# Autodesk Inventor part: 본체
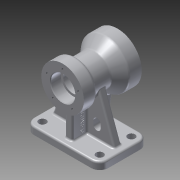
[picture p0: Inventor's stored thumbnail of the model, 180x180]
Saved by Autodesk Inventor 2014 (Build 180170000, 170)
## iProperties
Created: 2015-08
Part Number: 본체
Material: 알루미늄 6061
Document SubType Name: Modeling
Designer: SCD-A09
Density: 2.71 g/cm^3
Appearance: 알루미늄 - 평지
Mass: 1062.37 g
Surface Area: 750.557 cm^2
Volume: 392.018 cm^3
Author: SCD-A09
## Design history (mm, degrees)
sketch "스케치1"
  geometry: L1 (-61, 40)-(61, 40); L2 (61, 40)-(61, -40); L3 (61, -40)-(-61, -40); L4 (-61, -40)-(-61, 40); L5 (-61, 40)-(61, -40); L6 (61, 40)-(-61, -40); 1 further point
  constraints: 12 end point, 2 midpoint, 2 parallel, 1 horizontal, 1 perpendicular
  dimensions: "d0" = 122 distance of L2.end L3.end; "d1" = 80 distance of L1.end L2.end
extrude "돌출1" new body sketch "스케치1" distance "d2" = 12; taper "d3" = 0 deg
fillet "모깎기1" dims "d4" = 14
fillet "모깎기2" dims "d5" = 3
sketch "스케치3"
  geometry: L1 (0, 40)-(9, 40) reference; L2 (90, 63.67)-(90, -74.186); L3 (0, 26)-(0, -26) reference; L4 (90, 40)-(125, 40); L5 (125, 40)-(125, 20); L6 (125, 20)-(116, 14.804); L7 (116, 14.804)-(116, -13.315); L8 (116, -13.315)-(130, -30); L9 (130, -30)-(130, -50); L10 (130, -50)-(90, -50); 1 further point
  constraints: 16 end point, 4 perpendicular, 3 point on line, 2 parallel
  dimensions: "d7" = 90 distance between parallel lines of L3 L2; "d8" = 70 diameter of L5 L2; "d9" = 52 diameter of L7 L2; "d10" = 80 diameter of L9 L2; "d11" = 20 distance of L4.end L5.end; "d12" = 20 distance of L8.end L9.end; "d13" = 60 deg angle of L7 L6; "d14" = 40 deg angle of L7 L8; "d15" = 90 distance between parallel lines of L10 L4
revolve "회전1" sketch "스케치3" stored, may be unused: angle "d16" = 90 deg
sketch "스케치4"
  geometry: L1 (61, 9)-(61, 0) reference; L2 (61, 0)-(-61, 0) reference; L3 (-61, 0)-(-61, 9) reference; L4 (-58, 12)-(58, 12) reference; L5 (51, 12)-(20.667, 95.339); L6 (-51, 12)-(-20.234, 96.53); L7 (20.667, 95.339)-(-20.234, 96.53); L8 (51, 12)-(-51, 12); C1 r 26 at (0, 90) reference; A1 r 3 centre (58, 9) between (61, 9) and (58, 12) reference; A2 r 3 centre (-58, 9) between (-58, 12) and (-61, 9) reference; 1 further point
  constraints: 8 end point, 2 point on line, 1 collinear
  dimensions: "d22" = 70 deg angle of L4 L5; "d23" = 70 deg angle of L4 L6; "d24" = 10 horizontal distance of L5.start L1.start; "d25" = 10 horizontal distance of L3.end L6.start
extrude "돌출2" join sketch "스케치4" stored distance "d26" = 12; taper "d27" = 0 deg
sketch "스케치5"
  geometry: L1 (12, 37)-(12, 6) reference; L2 (12, 6)-(64, 6) reference; L3 (64, 6)-(64, 14.804) reference; L4 (64, 14.804)-(55, 20) reference; L5 (55, 20)-(55, 40) reference; L6 (55, 40)-(125, 40) reference; L7 (125, 40)-(125, 20) reference; L8 (125, 20)-(116, 14.804) reference; L9 (116, 14.804)-(116, -13.315) reference; L10 (116, -13.315)-(130, -30) reference; L11 (130, -30)-(130, -50) reference; L12 (130, -50)-(50, -50) reference; L13 (50, -50)-(50, -30) reference; L14 (50, -30)-(64, -13.315) reference; L15 (64, -13.315)-(64, -6) reference; L16 (64, -6)-(12, -6) reference; L17 (12, -6)-(12, -37) reference; L18 (9, -40)-(0, -40) reference; L19 (0, -40)-(0, 40) reference; L20 (0, 40)-(9, 40) reference; L21 (12, 30)-(82.096, 30); L22 (82.096, 30)-(82.096, -42.36); L23 (82.096, -42.36)-(12, -30); L24 (12, 30)-(12, -30); A1 r 3 centre (9, 37) between (12, 37) and (9, 40) reference; A2 r 3 centre (9, -37) between (9, -40) and (12, -37) reference; 3 further points
  constraints: 8 end point, 5 point on line, 1 collinear, 1 parallel, 1 perpendicular
  dimensions: "d28" = 10 distance from line of L19.end L21; "d29" = 10 vertical distance of L18.start L23.end; "d30" = 80 deg angle of L17 L23
extrude "돌출3" join sketch "스케치5" stored distance "d31" = 12; taper "d32" = 0 deg
sketch "스케치6"
  geometry: C1 r 6 at (-47, -26); C2 r 6 at (-47, 26); C3 r 6 at (47, 26); C4 r 6 at (47, -26); A1 r 11 centre (-47, -26) between (-58, -26) and (-47, -37) reference; A2 r 11 centre (47, -26) between (47, -37) and (58, -26) reference; A3 r 11 centre (47, 26) between (58, 26) and (47, 37) reference; A4 r 11 centre (-47, 26) between (-47, 37) and (-58, 26) reference; 1 further point
  constraints: 4 centre point, 4 coincident
  dimensions: "d34" = 12 diameter of C1; "d35" = 12 diameter of C2; "d36" = 12 diameter of C3; "d37" = 12 diameter of C4
extrude "돌출4" cut sketch "스케치6" stored distance "d38" = 12; taper "d39" = 0 deg
sketch "스케치7"
  geometry: L1 (-6, 12)-(-6, 64.702) reference; L2 (-6, 12)-(-51, 12) reference; L3 (-58, 12)-(-51, 12) reference; L4 (-51, 12)-(-6, 12) reference; L5 (-6, 12)-(-6, 64.702) reference; L6 (-51, 12)-(-25.091, 83.185) reference; L7 (-61, 0)-(-61, 9) reference; L8 (61, 0)-(-61, 0) reference; L9 (61, 9)-(61, 0) reference; L10 (51, 12)-(58, 12) reference; L11 (6, 12)-(51, 12) reference; L12 (6, 64.702)-(6, 12) reference; L13 (25.091, 83.185)-(51, 12) reference; L14 (-22.5, 30)-(-22.5, 36); L15 (-28.5, 30)-(-28.5, 36); L16 (-16.5, 36)-(-16.5, 30); L17 (25.5, 30)-(25.5, 36); L18 (19.5, 30)-(19.5, 36); L19 (31.5, 36)-(31.5, 30); A1 r 26 centre (0, 90) between (-25.091, 83.185) and (-6, 64.702) reference; A2 r 26 centre (0, 90) between (-25.091, 83.185) and (-6, 64.702) reference; A3 r 3 centre (-58, 9) between (-58, 12) and (-61, 9) reference; A4 r 3 centre (58, 9) between (61, 9) and (58, 12) reference; A5 r 26 centre (0, 90) between (6, 64.702) and (25.091, 83.185) reference; A6 r 26 centre (0, 90) between (25.091, 83.185) and (-25.091, 83.185) reference; A7 r 6 centre (-22.5, 30) between (-28.5, 30) and (-16.5, 30); A8 r 6 centre (-22.5, 36) between (-16.5, 36) and (-28.5, 36); A9 r 6 centre (25.5, 30) between (19.5, 30) and (31.5, 30); A10 r 6 centre (25.5, 36) between (31.5, 36) and (19.5, 36); 3 further points
  constraints: 16 end point, 8 point on circle, 8 tangent, 5 parallel, 4 centre point, 2 midpoint, 1 equal radius, 1 horizontal alignment
  dimensions: "d41" = 12 distance between parallel lines of L16 L15; "d42" = 18 dimension on A7 A8; "d43" = 18 distance from line of L2 L14.start; "d44" = 48 distance of point (25.5, 33) point (-22.5, 33); "d45" = 22.5 horizontal distance of A1.centre point (-22.5, 33)
extrude "돌출5" cut sketch "스케치7" stored distance "d46" = 12; taper "d47" = 0 deg
fillet "모깎기3" dims "d48" = 5
fillet "모깎기4" dims "d49" = 3
fillet "모깎기5" dims "d50" = 3
sketch "스케치8"
  geometry: C1 r 40 at (0, 0) reference; C2 r 26 at (0, 0); 1 further point
  constraints: 1 centre point, 1 coincident
  dimensions: "d51" = 52 diameter of C2
extrude "돌출6" cut sketch "스케치8" distance "d52" = 20; taper "d53" = 0 deg
sketch "스케치9"
  geometry: C1 r 26 at (0, 0) reference; C2 r 19 at (0, 0); 1 further point
  constraints: 1 centre point, 1 coincident
  dimensions: "d54" = 38 diameter of C2
extrude "돌출7" cut sketch "스케치9" distance "d55" = 3; taper "d56" = 0 deg
sketch "스케치10"
  geometry: C1 r 35 at (0, 0) reference; C2 r 20 at (0, 0); 1 further point
  constraints: 1 centre point, 1 coincident
  dimensions: "d57" = 40 diameter of C2
extrude "돌출8" cut sketch "스케치10" distance "d58" = 17; taper "d59" = 0 deg
sketch "스케치11"
  geometry: C1 r 20 at (0, 0) reference; C2 r 16 at (0, 0); 1 further point
  constraints: 1 centre point, 1 coincident
  dimensions: "d60" = 32 diameter of C2
extrude "돌출9" cut sketch "스케치11" stored distance "d61" = 40; taper "d62" = 0 deg
sketch "스케치12" dims "d63" = 66
  geometry: C1 r 40 at (0, 0) reference; 7 further points
  constraints: 1 coincident, 1 vertical alignment, 8 other
  dimensions: "d66" = 360 deg dimension on point (0, 0) point (0, 33) (derived)
hole "구멍1" sketch "스케치12" at (0, 33), (-31.385, 10.198), (-19.397, -26.698), (19.397, -26.698), (31.385, 10.198) diameter "d68" = 3.459; stored, may be unused: countersink angle "d72" = 90 deg, drill point angle "d74" = 118 deg; dims "d69" = 10, "d70" = 4, "d71" = 2, "d73" = 13
sketch "스케치13" dims "d75" = 54
  geometry: C1 r 35 at (0, 0) reference; 7 further points
  constraints: 1 coincident, 1 vertical alignment, 8 other
  dimensions: "d78" = 360 deg dimension on point (0, 0) point (0, 27) (derived)
hole "구멍2" sketch "스케치13" at (0, 27), (-25.679, 8.343), (-15.87, -21.843), (15.87, -21.843), (25.679, 8.343) diameter "d80" = 3.459; stored, may be unused: countersink angle "d84" = 90 deg, drill point angle "d86" = 118 deg; dims "d81" = 10, "d82" = 4, "d83" = 2, "d85" = 13
fillet "모깎기6" dims "d87" = 0.3
fillet "모깎기7" dims "d88" = 3
chamfer "모따기1" distance "d89" = 1; stored, may be unused: second distance "d90" = 2, angle "d91" = 45 deg
node "작업 평면1"
sketch "스케치14"
  geometry: L1 (-37, 12)-(-26, 12) reference; L2 (-30, 52.119)-(-30, 15) reference; 2 further points
  constraints: 1 other
  dimensions: "d93" = 24 distance from line of L1 point (-14, 36); "d94" = 16 distance from line of point (-14, 36) L2
feature "엠보싱1" sketch "스케치14" dims "d0" = 122, "d1" = 80, "d95" = 0.5, "d96" = 0
node "솔리드1"
node "절단 모서리 투영1"
node "절단 모서리 투영2"
node "절단 모서리 투영3"
other parameters: "d92" = 104.75
